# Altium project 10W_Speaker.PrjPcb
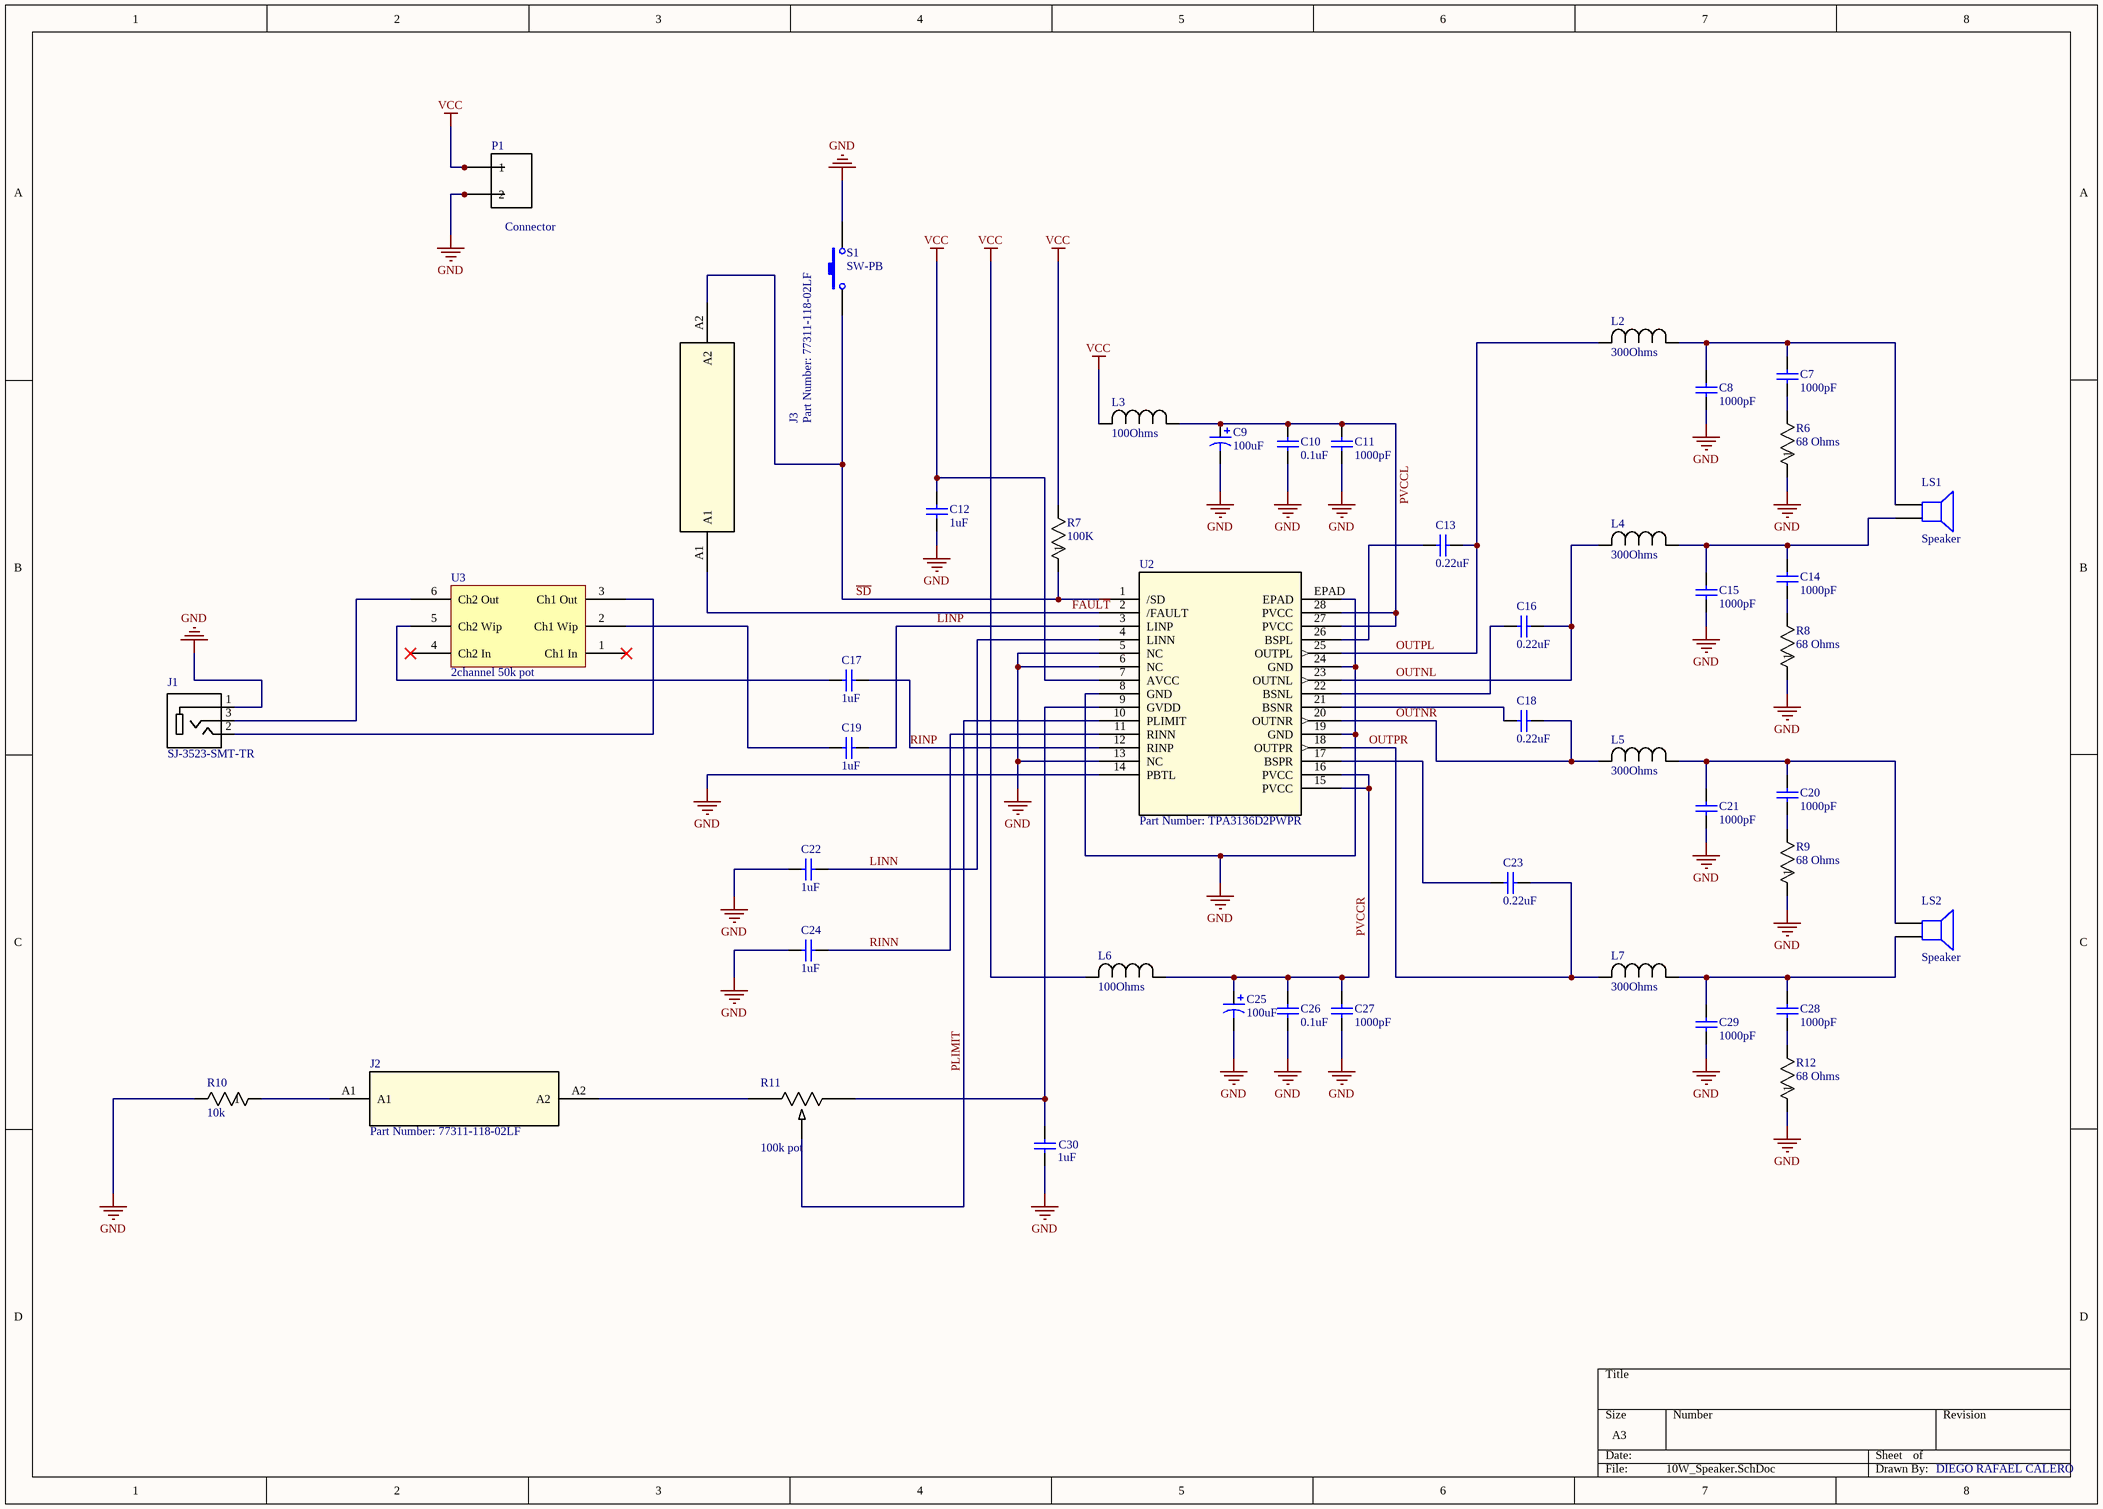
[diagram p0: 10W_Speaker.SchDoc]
1 sheet, 46 parts. Net scope: global (net labels, ports and power ports of the same name join across sheets).
Board file: 10W_Speaker.PcbDoc

## Sheet 10W_Speaker.SchDoc
size A3

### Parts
C7  1000pF  [1000pF (1206 case)]
C8  1000pF  [1000pF (1206 case)]
C9  100uF  [100uF electrolytic cap]
C10  0.1uF  [0.1uF (1206 case)]
C11  1000pF  [1000pF (1206 case)]
C12  1uF  [1uF (1206 case)]
C13  0.22uF  [0.22uF (1206 case)]
C14  1000pF  [1000pF (1206 case)]
C15  1000pF  [1000pF (1206 case)]
C16  0.22uF  [0.22uF (1206 case)]
C17  1uF  [1uF (1206 case)]
C18  0.22uF  [0.22uF (1206 case)]
C19  1uF  [1uF (1206 case)]
C20  1000pF  [1000pF (1206 case)]
C21  1000pF  [1000pF (1206 case)]
C22  1uF  [1uF (1206 case)]
C23  0.22uF  [0.22uF (1206 case)]
C24  1uF  [1uF (1206 case)]
C25  100uF  [100uF electrolytic cap]
C26  0.1uF  [0.1uF (1206 case)]
C27  1000pF  [1000pF (1206 case)]
C28  1000pF  [1000pF (1206 case)]
C29  1000pF  [1000pF (1206 case)]
C30  1uF  [1uF (1206 case)]
J1  SJ-3523-SMT-TR  [Audio Jack 3.5mm]
J2  Part Number: 77311-118-02LF  [Jumper]
J3  Part Number: 77311-118-02LF  [Jumper]
L2  300Ohms  [300 Ohms Ferrite Bead (0805 case)]
L3  100Ohms  [100 ohms ferrite]
L4  300Ohms  [300 Ohms Ferrite Bead (0805 case)]
L5  300Ohms  [300 Ohms Ferrite Bead (0805 case)]
L6  100Ohms  [100 ohms ferrite]
L7  300Ohms  [300 Ohms Ferrite Bead (0805 case)]
LS1  Speaker  [Banana Plug]
LS2  Speaker  [Banana Plug]
P1  Connector  [Connector]
R6  68 Ohms  [68 Ohms (0805 case)]
R7  100K  [100K Ohms (0805 case)]
R8  68 Ohms  [68 Ohms (0805 case)]
R9  68 Ohms  [68 Ohms (0805 case)]
R10  10k  [0.22uF (1206 case)]
R11  100k pot  [100k trimmer]
R12  68 Ohms  [68 Ohms (0805 case)]
S1  SW-PB  [E switch]
U2  Part Number: TPA3136D2PWPR  [TPA3136_PWP28_2p4X3.4-M]
U3  2channel 50k pot  [50K Ohms Carbon Log]

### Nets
GND: C8.1 C9.2 C10.1 C11.1 C12.1 C15.1 C21.1 C22.1 C24.1 C25.2 C26.1 C27.1 C29.1 C30.1 J1.1 P1.2.1(2) P1.2.2 R6.1 R8.1 R9.1 R10.2 R12.1 S1.2 U2.5(NC) U2.6(NC) U2.8(GND) U2.13(NC) U2.14(PBTL) U2.19(GND) U2.24(GND) U2.EPAD
VCC: C12.2 L3.2 L6.2 P1.1.1(1) P1.1.2 R7.2 U2.7(AVCC)
~{FAULT}: J3.A1 U2.2(/FAULT)
~{SD}: J3.A2 R7.1 S1.1 U2.1(/SD)
LINN: C22.2 U2.4(LINN)
LINP: C19.2 U2.3(LINP)
OUTNL: C16.2 L4.2 U2.23(OUTNL)
OUTNR: C18.2 L5.2 U2.20(OUTNR)
OUTPL: C13.2 L2.2 U2.25(OUTPL)
OUTPR: C23.2 L7.2 U2.18(OUTPR)
PLIMIT: R11.2 U2.10(PLIMIT)
PVCCL: C9.1 C10.2 C11.2 L3.1 U2.27(PVCC) U2.28(PVCC)
PVCCR: C25.1 C26.2 C27.2 L6.1 U2.15(PVCC) U2.16(PVCC)
RINN: C24.2 U2.11(RINN)
RINP: C17.2 U2.12(RINP)
NetC7_1: C7.1 R6.2
NetC7_2: C7.2 C8.2 L2.1 LS1.1
NetC13_1: C13.1 U2.26(BSPL)
NetC14_1: C14.1 R8.2
NetC14_2: C14.2 C15.2 L4.1 LS1.2
NetC16_1: C16.1 U2.22(BSNL)
NetC17_1: C17.1 U3.5(Ch2_Wip)
NetC18_1: C18.1 U2.21(BSNR)
NetC19_1: C19.1 U3.2(Ch1_Wip)
NetC20_1: C20.1 R9.2
NetC20_2: C20.2 C21.2 L5.1 LS2.1
NetC23_1: C23.1 U2.17(BSPR)
NetC28_1: C28.1 R12.2
NetC28_2: C28.2 C29.2 L7.1 LS2.2
NetC30_2: C30.2 R11.1 U2.9(GVDD)
NetJ1_2: J1.2 U3.3(Ch1_Out)
NetJ1_3: J1.3 U3.6(Ch2_Out)
NetJ2_A1: J2.A1 R10.1
NetJ2_A2: J2.A2 R11.3

Not connected (* = marked no-connect by the designer): U3 1(Ch1_In)* 4(Ch2_In)*

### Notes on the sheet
- DIEGO RAFAEL CALERO

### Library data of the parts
C7 C8 C11 C13-C16 C18 C20 C21 C23 C27-C29 = Cap Semi: Capacitor (Semiconductor SIM Model)
C9 = Cap Pol1
C10 C12 C17 C19 C22 C24 C26 C30 = Cap Semi: Capacitor (Semiconductor SIM Model); Value: 0.22uF
C25 = Cap Pol1: Polarized Capacitor (Radial)
J1 = SJ-3523-SMT-TR: 3.5 mm, Stereo, Right Angle, Surface Mount _SMT_, Audio Jack Connector; MF: CUI Inc.
J2 J3 = 77311-118-02LF: No Description Available; Vendor: Amphenol FCI; Built_By: EMA_UL_Team
L2-L7 = 300 Ohms Ferriter Bead: No Description Available; Built_By: EMA_UL_Team; Type: DEV
LS1 LS2 = Speaker: Loudspeaker
P1 = 1929517: Conn Terminal Block 2 POS 10.16mm Solder ST Thru-Hole 57A; MF: Phoenix Contact
R6 R8-R10 R12 = RMCF0805FT68R0: No Description Available; Vendor: Stackpole International; Built_By: EMA_UL_Team
R7 = RMCF0805FT100K: No Description Available; Vendor: Stackpole International; Built_By: EMA_UL_Team
R11 = 3386P-1-104LF: No Description Available; Vendor: Bourns Electronics; Built_By: EMA_UL_Team
S1 = SW-PB: Switch
U2 = TPA3136D2PWPR: No Description Available; Vendor: Texas Instruments; Built_By: EMA_Molly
